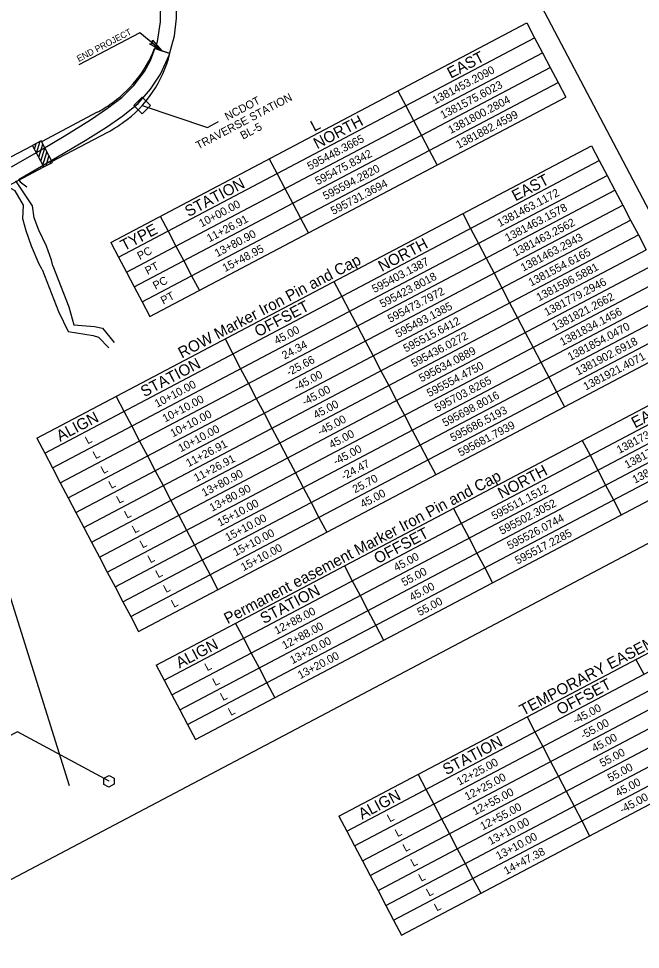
# Model space of a CAD drawing. Extents: x 1379448 to 1382868, y 593769 to 596827.
# Drawn here: x 1381695 to 1382473, y 594560 to 595724 of the extents above; entities that cross this region are included whole.
import ezdxf

# ---------------------------------------------------------------- set-up
doc = ezdxf.new("R2010")
doc.units = 0
for name, color, linetype in [('CTL GPS Vertical CELL', 7, 'Continuous'), ('CTL GPS Vertical Leader', 7, 'Continuous'), ('CTL Sheet Border CELL', 7, 'Continuous'), ('CTL Sheet Notes CELL', 7, 'Continuous'), ('CTL Sheet Table Cell', 7, 'Continuous'), ('CTL Sheet Text', 7, 'Continuous'), ('CTL Supplemental Horizontal and Vertical CELL', 7, 'Continuous'), ('CTL Supplemental Horizontal and Vertical Leader', 7, 'Continuous'), ('CTL Supplemental Horizontal and Vertical Text', 7, 'Continuous'), ('Exist Hydro Stream or Body of Water', 7, 'Continuous'), ('Exist Roads EOP', 7, 'Continuous'), ('Exist Structure Major Bridge WW', 7, 'Continuous'), ('Exist Utilities Power UG Cable', 7, 'Continuous'), ('Prop Horizontal Alignment Station Label', 7, 'Continuous'), ('Prop Shade Medium', 7, 'Continuous'), ('Prop Terminator CELL', 7, 'Continuous'), ('Scratch_Level_8', 7, 'Continuous'), ('Sheet Layout Profile Border Port 1', 7, 'Continuous')]:
    doc.layers.add(name, color=color, linetype=linetype)

msp = doc.modelspace()

# ---------------------------------------------------------------- linework, layer by layer
at = {"layer": 'CTL GPS Vertical CELL'}
msp.add_line((1381808.5, 594770.5), (1381808.5, 594770.5), dxfattribs=at)
msp.add_lwpolyline([(1381802, 594774.3), (1381808.5, 594777.9), (1381815, 594774.3), (1381814.9, 594766.9), (1381808.4, 594763.1), (1381802, 594766.7)], close=True, dxfattribs=at)
at = {"layer": 'CTL GPS Vertical Leader'}
msp.add_lwpolyline([(1381808.5, 594770.5), (1381694, 594832.4), (1381680.1, 594825.1)], dxfattribs=at)
at = {"layer": 'CTL Sheet Border CELL'}
msp.add_lwpolyline([(1381803.8, 596774.4), (1379496.1, 595557.9), (1380347.7, 593942.5), (1382655.4, 595159.1)], close=True, dxfattribs=at)
at = {"layer": 'CTL Sheet Table Cell'}
for p, q in [((1381810.7, 595444), (1382330.8, 595718.3)), ((1382330.8, 595718.3), (1382340.6, 595699.7)), ((1381820.5, 595425.5), (1382340.6, 595699.7)), ((1382340.6, 595699.7), (1382350.4, 595681.1)), ((1381830.3, 595406.9), (1382350.4, 595681.1)), ((1382350.4, 595681.1), (1382360.2, 595662.5)), ((1381840, 595388.3), (1382360.2, 595662.5)), ((1382360.2, 595662.5), (1382370, 595644)), ((1381849.8, 595369.7), (1382370, 595644)), ((1382370, 595644), (1382379.8, 595625.4)), ((1381859.6, 595351.2), (1382379.8, 595625.4)), ((1382169.8, 595633.4), (1382179.6, 595614.8)), ((1382179.6, 595614.8), (1382189.4, 595596.2)), ((1382189.4, 595596.2), (1382199.2, 595577.7)), ((1382199.2, 595577.7), (1382209, 595559.1)), ((1381718.2, 595199.2), (1382411.7, 595564.9)), ((1382411.7, 595564.9), (1382421.5, 595546.3)), ((1382209, 595559.1), (1382218.8, 595540.5)), ((1381728, 595180.7), (1382421.5, 595546.3)), ((1382008.8, 595548.5), (1382018.6, 595529.9)), ((1382421.5, 595546.3), (1382431.3, 595527.7)), ((1382018.6, 595529.9), (1382028.4, 595511.4)), ((1381737.7, 595162.1), (1382431.3, 595527.7)), ((1382431.3, 595527.7), (1382441.1, 595509.1)), ((1381747.5, 595143.5), (1382441.1, 595509.1)), ((1382028.4, 595511.4), (1382038.2, 595492.8)), ((1382441.1, 595509.1), (1382450.9, 595490.5)), ((1381757.3, 595124.9), (1382450.9, 595490.5)), ((1382038.2, 595492.8), (1382048, 595474.2)), ((1382450.9, 595490.5), (1382460.7, 595472)), ((1381767.1, 595106.3), (1382460.7, 595472)), ((1381872.6, 595476.7), (1381882.4, 595458.1)), ((1382048, 595474.2), (1382057.8, 595455.6)), ((1382250.7, 595480), (1382260.5, 595461.4)), ((1382460.7, 595472), (1382470.4, 595453.4)), ((1382260.5, 595461.4), (1382270.3, 595442.8)), ((1381776.9, 595087.8), (1382470.4, 595453.4)), ((1381882.4, 595458.1), (1381892.2, 595439.5)), ((1382470.4, 595453.4), (1382480.2, 595434.8)), ((1381810.7, 595444), (1381820.5, 595425.5)), ((1381892.2, 595439.5), (1381902, 595421)), ((1382270.3, 595442.8), (1382280.1, 595424.2)), ((1381786.7, 595069.2), (1382480.2, 595434.8)), ((1381820.5, 595425.5), (1381830.3, 595406.9)), ((1381796.5, 595050.6), (1382490, 595416.2)), ((1381902, 595421), (1381911.8, 595402.4)), ((1382280.1, 595424.2), (1382289.9, 595405.7)), ((1381830.3, 595406.9), (1381840, 595388.3)), ((1381911.8, 595402.4), (1381921.6, 595383.8)), ((1382289.9, 595405.7), (1382299.7, 595387.1)), ((1381806.3, 595032), (1382499.8, 595397.7)), ((1382089.7, 595395.1), (1382099.5, 595376.5)), ((1381816.1, 595013.5), (1382509.6, 595379.1)), ((1381840, 595388.3), (1381849.8, 595369.7)), ((1382299.7, 595387.1), (1382309.4, 595368.5)), ((1381849.8, 595369.7), (1381859.6, 595351.2)), ((1382099.5, 595376.5), (1382109.3, 595357.9)), ((1382309.4, 595368.5), (1382319.2, 595349.9)), ((1381825.9, 594994.9), (1382519.4, 595360.5)), ((1382109.3, 595357.9), (1382119.1, 595339.4)), ((1382319.2, 595349.9), (1382329, 595331.4)), ((1381835.7, 594976.3), (1382529.2, 595341.9)), ((1382119.1, 595339.4), (1382128.9, 595320.8)), ((1381845.5, 594957.7), (1382539, 595323.4)), ((1381953.5, 595323.3), (1381963.3, 595304.7)), ((1382128.9, 595320.8), (1382138.7, 595302.2)), ((1382329, 595331.4), (1382338.8, 595312.8)), ((1382338.8, 595312.8), (1382348.6, 595294.2)), ((1381963.3, 595304.7), (1381973, 595286.1)), ((1382138.7, 595302.2), (1382148.5, 595283.6)), ((1381973, 595286.1), (1381982.8, 595267.6)), ((1382348.6, 595294.2), (1382358.4, 595275.6)), ((1381867.6, 594915.7), (1382561.2, 595281.3)), ((1382148.5, 595283.6), (1382158.2, 595265.1)), ((1382358.4, 595275.6), (1382368.2, 595257.1)), ((1381877.4, 594897.1), (1382571, 595262.7)), ((1381982.8, 595267.6), (1381992.6, 595249)), ((1382158.2, 595265.1), (1382168, 595246.5)), ((1381817.2, 595251.5), (1381827, 595232.9)), ((1382368.2, 595257.1), (1382378, 595238.5)), ((1381887.2, 594878.5), (1382580.7, 595244.2)), ((1381992.6, 595249), (1382002.4, 595230.4)), ((1382168, 595246.5), (1382177.8, 595227.9)), ((1381827, 595232.9), (1381836.8, 595214.3)), ((1382002.4, 595230.4), (1382012.2, 595211.8)), ((1382177.8, 595227.9), (1382187.6, 595209.3)), ((1381897, 594860), (1382590.5, 595225.6)), ((1381836.8, 595214.3), (1381846.6, 595195.7)), ((1381906.8, 594841.4), (1382600.3, 595207)), ((1382012.2, 595211.8), (1382022, 595193.2)), ((1382187.6, 595209.3), (1382197.4, 595190.8)), ((1381718.2, 595199.2), (1381728, 595180.7)), ((1381846.6, 595195.7), (1381856.4, 595177.2)), ((1382022, 595193.2), (1382031.8, 595174.7)), ((1382400.2, 595196.4), (1382410, 595177.9)), ((1381728, 595180.7), (1381737.7, 595162.1)), ((1381916.6, 594822.8), (1382610.1, 595188.4)), ((1382197.4, 595190.8), (1382207.2, 595172.2)), ((1381856.4, 595177.2), (1381866.2, 595158.6)), ((1382031.8, 595174.7), (1382041.6, 595156.1)), ((1382207.2, 595172.2), (1382217, 595153.6)), ((1382410, 595177.9), (1382419.8, 595159.3)), ((1381737.7, 595162.1), (1381747.5, 595143.5)), ((1381866.2, 595158.6), (1381876, 595140)), ((1382419.8, 595159.3), (1382429.5, 595140.7)), ((1382041.6, 595156.1), (1382051.4, 595137.5)), ((1381747.5, 595143.5), (1381757.3, 595124.9)), ((1381876, 595140), (1381885.8, 595121.4)), ((1382051.4, 595137.5), (1382061.2, 595118.9)), ((1382429.5, 595140.7), (1382439.3, 595122.1)), ((1381757.3, 595124.9), (1381767.1, 595106.3)), ((1381885.8, 595121.4), (1381895.6, 595102.8)), ((1382061.2, 595118.9), (1382071, 595100.4)), ((1382239.2, 595111.6), (1382249, 595093)), ((1382439.3, 595122.1), (1382449.1, 595103.6)), ((1381767.1, 595106.3), (1381776.9, 595087.8)), ((1381895.6, 595102.8), (1381905.4, 595084.3)), ((1382071, 595100.4), (1382080.8, 595081.8)), ((1381776.9, 595087.8), (1381786.7, 595069.2)), ((1382249, 595093), (1382258.8, 595074.4)), ((1381905.4, 595084.3), (1381915.2, 595065.7)), ((1381786.7, 595069.2), (1381796.5, 595050.6)), ((1381915.2, 595065.7), (1381925, 595047.1)), ((1382258.8, 595074.4), (1382268.5, 595055.8)), ((1382268.5, 595055.8), (1382278.3, 595037.3)), ((1381796.5, 595050.6), (1381806.3, 595032)), ((1381925, 595047.1), (1381934.8, 595028.5)), ((1381806.3, 595032), (1381816.1, 595013.5)), ((1382102.9, 595039.7), (1382112.7, 595021.2)), ((1382278.3, 595037.3), (1382288.1, 595018.7)), ((1381934.8, 595028.5), (1381944.5, 595010)), ((1382112.7, 595021.2), (1382122.5, 595002.6)), ((1381816.1, 595013.5), (1381825.9, 594994.9)), ((1381825.9, 594994.9), (1381835.7, 594976.3)), ((1382122.5, 595002.6), (1382132.3, 594984)), ((1382132.3, 594984), (1382142.1, 594965.4)), ((1381835.7, 594976.3), (1381845.5, 594957.7)), ((1381966.7, 594967.9), (1381976.5, 594949.3)), ((1382142.1, 594965.4), (1382151.9, 594946.9)), ((1381976.5, 594949.3), (1381986.3, 594930.8)), ((1381986.3, 594930.8), (1381996.1, 594912.2)), ((1381867.6, 594915.7), (1381877.4, 594897.1)), ((1381996.1, 594912.2), (1382005.9, 594893.6)), ((1381877.4, 594897.1), (1381887.2, 594878.5)), ((1382005.9, 594893.6), (1382015.7, 594875)), ((1381887.2, 594878.5), (1381897, 594860)), ((1381897, 594860), (1381906.8, 594841.4)), ((1381906.8, 594841.4), (1381916.6, 594822.8))]:
    msp.add_line(p, q, dxfattribs=at)
at = {"layer": 'CTL Supplemental Horizontal and Vertical CELL'}
msp.add_line((1381849.7, 595615.2), (1381849.7, 595615.2), dxfattribs=at)
msp.add_lwpolyline([(1381839.3, 595615.2), (1381849.8, 595625.7), (1381860.3, 595615.2), (1381849.8, 595604.7)], close=True, dxfattribs=at)
at = {"layer": 'CTL Supplemental Horizontal and Vertical Leader'}
msp.add_lwpolyline([(1381849.7, 595615.2), (1381931.4, 595587.7), (1381945.5, 595595.2)], dxfattribs=at)
at = {"layer": 'Exist Hydro Stream or Body of Water'}
for p, q in [((1381724.9, 595410.3), (1381721.3, 595416.8)), ((1381738.4, 595414.7), (1381736.5, 595421.9))]:
    msp.add_line(p, q, dxfattribs=at)
for points in [[(1381736.5, 595421.9), (1381730.4, 595439.3), (1381720.8, 595459.5), (1381715, 595474.6), (1381712.9, 595489.7), (1381695.2, 595515.9), (1381692.1, 595520.9)], [(1381721.3, 595416.8), (1381711.5, 595439.2), (1381704.9, 595458.4), (1381700.7, 595473.3), (1381701.7, 595490.7), (1381691, 595508.6), (1381680.3, 595514.3)], [(1381738.4, 595414.7), (1381758, 595363.5), (1381764.3, 595341), (1381790.4, 595338.9), (1381800.1, 595336.7), (1381815.1, 595319.1)], [(1381724.9, 595410.3), (1381745.2, 595357.8), (1381757.5, 595332.6), (1381788.6, 595327.7), (1381795.2, 595325.6), (1381808.1, 595312.1)]]:
    msp.add_lwpolyline(points, dxfattribs=at)
at = {"layer": 'Exist Roads EOP'}
for points in [[(1381695.4, 595522.7), (1381736.8, 595546.7), (1381778.6, 595571.3), (1381805.3, 595588.1), (1381825.8, 595602), (1381844.7, 595617.6), (1381860.5, 595635.4), (1381873, 595654.3), (1381883.8, 595678.2), (1381890.3, 595702.1), (1381892.9, 595724.3), (1381892.5, 595748), (1381889.9, 595776.2), (1381882.9, 595811.5), (1381872.7, 595847), (1381870.8, 595855), (1381871.9, 595862.1), (1381875.4, 595867.7)], [(1381686.7, 595538.6), (1381723.5, 595559.6), (1381752.3, 595576.7), (1381785.4, 595597.2), (1381806.7, 595611.6), (1381824.4, 595625.2), (1381839.6, 595640.2), (1381852.7, 595657.4), (1381860.2, 595671.3), (1381868.9, 595695.3), (1381872.9, 595719.8), (1381873.3, 595746.5), (1381871.4, 595770.4), (1381866.6, 595797.6), (1381860.1, 595823.8)]]:
    msp.add_lwpolyline(points, dxfattribs=at)
at = {"layer": 'Exist Structure Major Bridge WW'}
msp.add_lwpolyline([(1381696.1, 595521.8), (1381697.4, 595519.7), (1381705.6, 595513.4)], dxfattribs=at)
at = {"layer": 'Exist Utilities Power UG Cable'}
msp.add_lwpolyline([(1381759.2, 594764.7), (1381385.9, 595955), (1381245.3, 596401.9)], dxfattribs=at)
at = {"layer": 'Prop Horizontal Alignment Station Label'}
for p, q in [((1381847, 595706), (1381770.7, 595665.8)), ((1381875, 595683.2), (1381847, 595706))]:
    msp.add_line(p, q, dxfattribs=at)
at = {"layer": 'Prop Shade Medium'}
msp.add_line((1381884.5, 595680.1), (1381865.5, 595686.3), dxfattribs=at)
for points in [[(1381884.5, 595680.1), (1381875, 595683.2), (1381865.5, 595686.3)], [(1381793.8, 595606.7), (1381724, 595569.9), (1381737, 595545.1), (1381806.8, 595581.9)]]:
    msp.add_lwpolyline(points, dxfattribs=at)
for centre, radius, start, end in [((1381725.7, 595740.8), 150, 303.5175, 338.7034), ((1381738.8, 595715.8), 150, 305.503, 346.2431), ((1381728.5, 595730.5), 140, 297.7977, 304.9041), ((1381728.5, 595730.5), 168, 297.7977, 305.4691)]:
    msp.add_arc(centre, radius, start, end, dxfattribs=at)
at = {"layer": 'Prop Terminator CELL'}
msp.add_lwpolyline([(1381863, 595696.9), (1381875, 595683.2), (1381858.9, 595692.1), (1381862.7, 595693.1)], close=True, dxfattribs=at)
at = {"layer": 'Scratch_Level_8'}
for p, q in [((1382095.9, 594726.9), (1382789.4, 595092.5)), ((1382105.7, 594708.3), (1382799.2, 595073.9)), ((1382115.5, 594689.7), (1382809, 595055.3)), ((1382125.3, 594671.1), (1382818.8, 595036.8)), ((1382135.1, 594652.6), (1382828.6, 595018.2)), ((1382144.9, 594634), (1382838.4, 594999.6)), ((1382154.6, 594615.4), (1382848.2, 594981)), ((1382164.4, 594596.8), (1382858, 594962.4)), ((1382174.2, 594578.3), (1382867.8, 594943.9)), ((1382467.4, 594922.7), (1382477.2, 594904.2)), ((1382331.2, 594850.9), (1382341, 594832.3)), ((1382341, 594832.3), (1382350.8, 594813.8)), ((1382350.8, 594813.8), (1382360.6, 594795.2)), ((1382360.6, 594795.2), (1382370.4, 594776.6)), ((1382195, 594779.1), (1382204.8, 594760.5)), ((1382370.4, 594776.6), (1382380.2, 594758)), ((1382204.8, 594760.5), (1382214.6, 594741.9)), ((1382380.2, 594758), (1382390, 594739.5)), ((1382214.6, 594741.9), (1382224.3, 594723.4)), ((1382390, 594739.5), (1382399.7, 594720.9)), ((1382095.9, 594726.9), (1382105.7, 594708.3)), ((1382224.3, 594723.4), (1382234.1, 594704.8)), ((1382399.7, 594720.9), (1382409.5, 594702.3)), ((1382105.7, 594708.3), (1382115.5, 594689.7)), ((1382234.1, 594704.8), (1382243.9, 594686.2)), ((1382115.5, 594689.7), (1382125.3, 594671.1)), ((1382243.9, 594686.2), (1382253.7, 594667.6)), ((1382125.3, 594671.1), (1382135.1, 594652.6)), ((1382253.7, 594667.6), (1382263.5, 594649.1)), ((1382135.1, 594652.6), (1382144.9, 594634)), ((1382263.5, 594649.1), (1382273.3, 594630.5)), ((1382144.9, 594634), (1382154.6, 594615.4)), ((1382154.6, 594615.4), (1382164.4, 594596.8)), ((1382164.4, 594596.8), (1382174.2, 594578.3))]:
    msp.add_line(p, q, dxfattribs=at)
at = {"layer": 'Sheet Layout Profile Border Port 1'}
for p, q in [((1381624.3, 595518.7), (1381712.8, 595565.3)), ((1381723.4, 595570.9), (1381712.8, 595565.3)), ((1381727, 595538.4), (1381712.8, 595565.3)), ((1381715.2, 595560.7), (1381717.4, 595567.8)), ((1381717.8, 595555.7), (1381722.4, 595570.4)), ((1381720.5, 595550.7), (1381725.5, 595566.9)), ((1381737.6, 595544), (1381723.4, 595570.9)), ((1381723.1, 595545.7), (1381728.1, 595561.9)), ((1381725.8, 595540.7), (1381730.8, 595556.9)), ((1381727, 595538.4), (1381737.6, 595544)), ((1381729.7, 595539.9), (1381733.4, 595551.9)), ((1381734.7, 595542.5), (1381736.1, 595546.9)), ((1381638.5, 595491.8), (1381727, 595538.4))]:
    msp.add_line(p, q, dxfattribs=at)

# ---------------------------------------------------------------- texts
at = {"layer": 'CTL Sheet Notes CELL'}
for s, p in [('EAST', (1382235.9, 595648.5)), ('NORTH', (1382068.8, 595560.3)), ('L', (1382065, 595582.1)), ('EAST', (1382316.8, 595495.1)), ('STATION', (1381907.9, 595475.5)), ('TYPE', (1381827.3, 595433)), ('NORTH', (1382149.7, 595406.9)), ('ROW Marker Iron Pin and Cap', (1381899.5, 595298.8)), ('OFFSET', (1381994.9, 595325.4)), ('STATION', (1381852.6, 595250.3)), ('EAST', (1382466.3, 595211.5)), ('ALIGN', (1381747.2, 595194.8)), ('NORTH', (1382299.2, 595123.4)), ('Permanent easement Marker Iron Pin and Cap', (1381956.8, 594966.7)), ('OFFSET', (1382144.4, 595041.8)), ('STATION', (1382002, 594966.8)), ('ALIGN', (1381896.7, 594911.2))]:
    msp.add_text(s, height=14, rotation=27.7977, dxfattribs=at).set_placement(p)
at = {"layer": 'CTL Sheet Text'}
for s, p in [('1381453.2090', (1382216.1, 595616.5)), ('1381575.6023', (1382225.9, 595598)), ('1381800.2804', (1382235.7, 595579.4)), ('1381882.4599', (1382245.5, 595560.8)), ('595448.3665', (1382059.5, 595534)), ('595475.8342', (1382069.3, 595515.4)), ('595594.2820', (1382079.1, 595496.8)), ('595731.3694', (1382088.9, 595478.2)), ('1381463.1172', (1382297, 595463.1)), ('10+00.00', (1381924.1, 595462.6)), ('1381463.1578', (1382306.8, 595444.6)), ('11+26.91', (1381933.9, 595444)), ('1381463.2562', (1382316.6, 595426)), ('13+80.90', (1381943.7, 595425.4)), ('1381463.2943', (1382326.4, 595407.4)), ('PC ', (1381846.9, 595421.9)), ('15+48.95', (1381953.5, 595406.8)), ('1381554.6165', (1382336.2, 595388.8)), ('595403.1387', (1382140.4, 595380.6)), ('PT ', (1381856.7, 595403.3)), ('1381596.5881', (1382346, 595370.3)), ('595423.8018', (1382150.2, 595362)), ('PC ', (1381866.5, 595384.8)), ('1381779.2946', (1382355.8, 595351.7)), ('PT ', (1381876.3, 595366.2)), ('595473.7972', (1382160, 595343.4)), ('1381821.2662', (1382365.6, 595333.1)), ('595493.1385', (1382169.8, 595324.8)), ('1381834.1456', (1382375.4, 595314.5)), ('595515.6412', (1382179.6, 595306.3)), ('1381854.0470', (1382385.2, 595295.9)), ('45.00', (1382018.1, 595316.1)), ('595436.0272', (1382189.4, 595287.7)), ('24.34', (1382027.9, 595297.5)), ('1381902.6918', (1382394.9, 595277.4)), ('595634.0889', (1382199.2, 595269.1)), ('-25.66', (1382033.3, 595276.6)), ('1381921.4071', (1382404.7, 595258.8)), ('595554.4750', (1382209, 595250.5)), ('-45.00', (1382043.1, 595258.1)), ('595703.8265', (1382218.8, 595232)), ('10+10.00', (1381868.7, 595237.3)), ('-45.00', (1382052.9, 595239.5)), ('10+10.00', (1381878.5, 595218.8)), ('595698.8016', (1382228.5, 595213.4)), ('45.00', (1382067.1, 595223.2)), ('595686.5193', (1382238.3, 595194.8)), ('10+10.00', (1381888.3, 595200.2)), ('-45.00', (1382072.5, 595202.3)), ('1381739.0873', (1382446.5, 595179.6)), ('10+10.00', (1381898.1, 595181.6)), ('595681.7939', (1382248.1, 595176.2)), ('45.00', (1382086.7, 595186.1)), ('1381743.7509', (1382456.3, 595161)), ('L', (1381781.8, 595191.5)), ('11+26.91', (1381907.9, 595163)), ('L', (1381791.6, 595172.9)), ('-45.00', (1382092.1, 595165.2)), ('1381767.3945', (1382466.1, 595142.4)), ('11+26.91', (1381917.7, 595144.5)), ('-24.47', (1382101.9, 595146.6)), ('L', (1381801.4, 595154.4)), ('13+80.90', (1381927.5, 595125.9)), ('L', (1381811.2, 595135.8)), ('25.70', (1382116.1, 595130.3)), ('13+80.90', (1381937.3, 595107.3)), ('45.00', (1382125.8, 595111.8)), ('595511.1512', (1382289.9, 595097)), ('L', (1381821, 595117.2)), ('15+10.00', (1381947.1, 595088.7)), ('595502.3052', (1382299.7, 595078.5)), ('L', (1381830.8, 595098.6)), ('15+10.00', (1381956.9, 595070.2)), ('595526.0744', (1382309.5, 595059.9)), ('L', (1381840.6, 595080.1)), ('15+10.00', (1381966.7, 595051.6)), ('595517.2285', (1382319.3, 595041.3)), ('L', (1381850.3, 595061.5)), ('15+10.00', (1381976.5, 595033)), ('L', (1381860.1, 595042.9)), ('45.00', (1382167.6, 595032.6)), ('L', (1381869.9, 595024.3)), ('55.00', (1382177.4, 595014)), ('45.00', (1382187.2, 594995.4)), ('L', (1381879.7, 595005.8)), ('L', (1381889.5, 594987.2)), ('55.00', (1382197, 594976.8)), ('12+88.00', (1382018.2, 594953.8)), ('12+88.00', (1382028, 594935.2)), ('13+20.00', (1382037.8, 594916.7)), ('13+20.00', (1382047.6, 594898.1)), ('L', (1381931.3, 594908)), ('L', (1381941.1, 594889.4)), ('L', (1381950.9, 594870.8)), ('L', (1381960.7, 594852.2))]:
    msp.add_text(s, height=10, rotation=27.7977, dxfattribs=at).set_placement(p)
at = {"layer": 'CTL Supplemental Horizontal and Vertical Text'}
for s, p in [('TRAVERSE STATION', (1381920.2, 595559.9)), ('NCDOT', (1381956.5, 595596)), ('BL-5', (1381975.9, 595572.3))]:
    msp.add_text(s, height=10, rotation=27.7977, dxfattribs=at).set_placement(p)
at = {"layer": 'Prop Horizontal Alignment Station Label'}
msp.add_text('END PROJECT', height=8, rotation=27.7977, dxfattribs=at).set_placement((1381770.7, 595669.4))
at = {"layer": 'Scratch_Level_8'}
for s, height, p in [('TEMPORARY EASEMENTS', 14, (1382326.3, 594852.3)), ('OFFSET', 14, (1382372.7, 594853)), ('-45.00', 10, (1382391.5, 594841.4)), ('-55.00', 10, (1382401.3, 594822.8)), ('STATION', 14, (1382230.3, 594777.9)), ('45.00', 10, (1382415.4, 594806.6)), ('55.00', 10, (1382425.2, 594788)), ('12+25.00', 10, (1382246.5, 594765)), ('55.00', 10, (1382435, 594769.4)), ('12+25.00', 10, (1382256.3, 594746.4)), ('45.00', 10, (1382444.8, 594750.9)), ('12+55.00', 10, (1382266, 594727.8)), ('ALIGN', 14, (1382124.9, 594722.4)), ('-45.00', 10, (1382450.2, 594730)), ('12+55.00', 10, (1382275.8, 594709.2)), ('L', 10, (1382159.5, 594719.1)), ('13+10.00', 10, (1382285.6, 594690.7)), ('L', 10, (1382169.3, 594700.6)), ('13+10.00', 10, (1382295.4, 594672.1)), ('L', 10, (1382179.1, 594682)), ('14+47.38', 10, (1382305.2, 594653.5)), ('L', 10, (1382188.9, 594663.4)), ('L', 10, (1382198.7, 594644.8)), ('L', 10, (1382208.5, 594626.3)), ('L', 10, (1382218.3, 594607.7))]:
    msp.add_text(s, height=height, rotation=27.7977, dxfattribs=at).set_placement(p)

doc.saveas('drawing.dxf')
